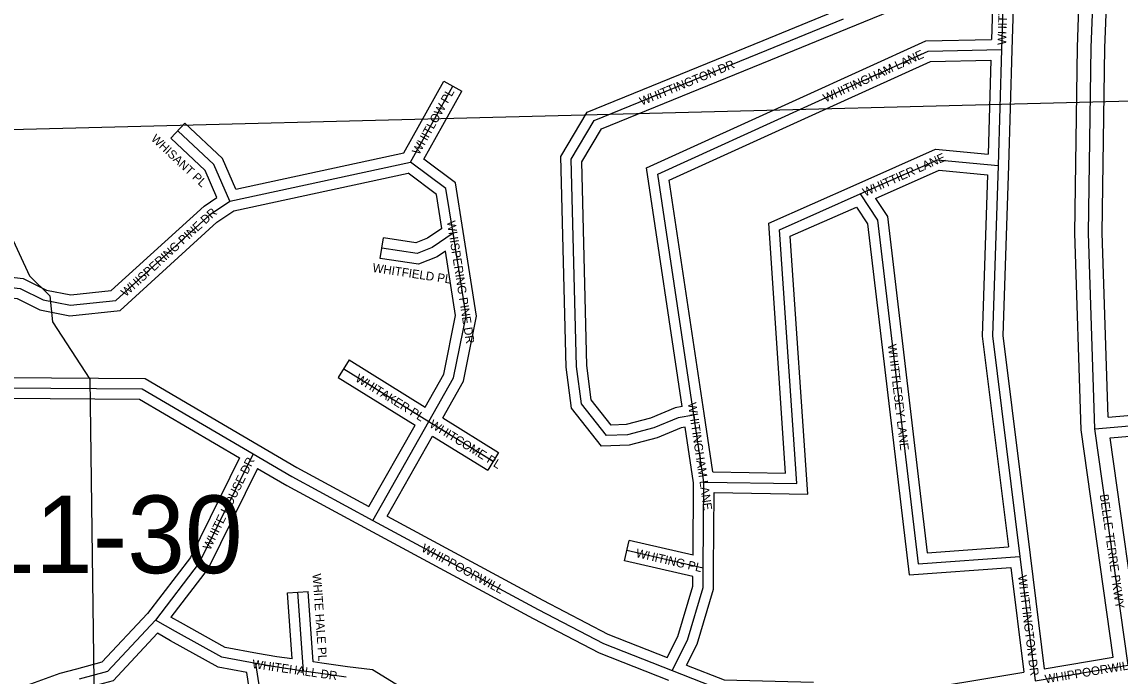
# Model space of a CAD drawing. Extents: x 457167 to 656239, y 1787309 to 1969297.
# Drawn here: x 581357 to 584541, y 1885990 to 1887885 of the extents above; entities that cross this region are included whole.
import ezdxf

# ---------------------------------------------------------------- set-up
doc = ezdxf.new("R2010")
doc.units = 0
for name, color, linetype in [('Level 1', 7, 'Continuous'), ('Level 2', 7, 'Continuous'), ('Level 22', 7, 'Continuous'), ('Level 23', 7, 'Continuous'), ('Level 31', 7, 'Continuous'), ('Level 32', 7, 'Continuous'), ('Level 34', 7, 'Continuous'), ('Level 7', 7, 'Continuous')]:
    doc.layers.add(name, color=color, linetype=linetype)

msp = doc.modelspace()

# ---------------------------------------------------------------- linework, layer by layer
at = {"layer": 'Level 1'}
msp.add_line((585126.331, 1887669.13), (579922.889, 1887536.016), dxfattribs=at)
at = {"layer": 'Level 22'}
for p, q in [((584457.098, 1887810.93), (584472.847, 1888226.538)), ((584564.332, 1886020.891), (584467.69, 1886706.173))]:
    msp.add_line(p, q, dxfattribs=at)
msp.add_lwpolyline([(584467.69, 1886706.173), (584449.383, 1887273.122), (584457.098, 1887810.93)], dxfattribs=at)
at = {"layer": 'Level 23'}
for p, q in [((584417.109, 1887811.974), (584432.875, 1888228.053)), ((584497.089, 1887809.885), (584512.819, 1888225.023)), ((584520.675, 1886044.017), (584427.782, 1886702.724)), ((584603.599, 1886028.903), (584511.802, 1886679.831))]:
    msp.add_line(p, q, dxfattribs=at)
for points in [[(584427.781, 1886702.725), (584409.373, 1887272.763), (584417.109, 1887811.974)], [(584506.633, 1886739.61), (584489.392, 1887273.481), (584497.089, 1887809.885)]]:
    msp.add_lwpolyline(points, dxfattribs=at)
at = {"layer": 'Level 31'}
for p, q in [((584206.055, 1888084.51), (584197.564, 1887804.888)), ((583516.949, 1887803.307), (583739.438, 1887894.145)), ((583016.266, 1887599.564), (583516.949, 1887803.307)), ((584197.564, 1887804.888), (584187.054, 1887469.269)), ((582483.302, 1887478.801), (582605.867, 1887698.56)), ((583200.746, 1887444.29), (583625.077, 1887636.912)), ((581959.255, 1887365.665), (582483.302, 1887478.801)), ((583305.287, 1886745.896), (583200.746, 1887444.29)), ((582289.695, 1886879.91), (582536.836, 1886727.052)), ((582374.698, 1886440.828), (582536.836, 1886727.052)), ((582536.836, 1886727.052), (582723.306, 1886612.136)), ((583334.167, 1886551.657), (583305.287, 1886745.896)), ((583332.406, 1886301.841), (583334.167, 1886551.657)), ((583332.406, 1886301.841), (583110.504, 1886353.187)), ((584250.699, 1886336.046), (584295.168, 1885975.957)), ((582172.819, 1886004.136), (582157.053, 1886232.896)), ((584295.168, 1885975.957), (584564.332, 1886020.891))]:
    msp.add_line(p, q, dxfattribs=at)
for points in [[(583625.077, 1887636.912), (583984.466, 1887800.575), (584197.564, 1887804.888)], [(583305.287, 1886745.896), (583259.471, 1886737.623), (583189.125, 1886708.671), (583113.072, 1886688.82), (583051.365, 1886686.396), (582979.029, 1886778.176), (582965.249, 1886886.931), (582949.574, 1887487.331), (583016.266, 1887599.564)], [(581959.255, 1887365.665), (581913.351, 1887471.94), (581808.909, 1887569.605)], [(583787.746, 1887386.411), (584011.207, 1887485.611), (584187.054, 1887469.269)], [(582606.933, 1887272.736), (582586.197, 1887401.869), (582483.302, 1887478.801)], [(584187.054, 1887469.269), (584171.151, 1886975.478), (584250.699, 1886336.046)], [(583334.167, 1886551.657), (583603.232, 1886547.128), (583553.461, 1887282.868), (583787.746, 1887386.411)], [(583787.746, 1887386.411), (583837.214, 1887310.313), (583955.503, 1886314.802), (584250.699, 1886336.046)], [(581243.166, 1887125.286), (581351.276, 1887112.341), (581418.319, 1887079.477), (581497.164, 1887064.046), (581628.864, 1887077.598), (581903.522, 1887327.958), (581959.255, 1887365.665)], [(582606.933, 1887272.736), (582546.739, 1887231.401), (582502.815, 1887214.033), (582400.434, 1887229.51)], [(582536.836, 1886727.052), (582608.331, 1886854.184), (582644.625, 1887033.386), (582606.933, 1887272.736)], [(581196.746, 1886817.377), (581307.761, 1886824.79), (581705.637, 1886821.441), (582026.812, 1886633.524)], [(584467.69, 1886706.173), (584713.267, 1886727.153), (585177.477, 1886817.535)], [(582026.812, 1886633.524), (581870.971, 1886317.47), (581743.734, 1886151.178)], [(582026.812, 1886633.524), (582139.59, 1886567.843), (582374.698, 1886440.828)], [(582374.698, 1886440.828), (582853.179, 1886182.785), (583042.865, 1886083.863), (583242.451, 1886005.287)], [(583242.451, 1886005.287), (583286.834, 1886093.201), (583331.66, 1886245.841), (583332.406, 1886301.841)], [(581743.734, 1886151.178), (581604.763, 1886002.73), (581522.66, 1885980.713)], [(582034.824, 1886025.866), (581935.944, 1886043.883), (581801.873, 1886118.335), (581743.734, 1886151.178)], [(581987.091, 1885535.05), (582028.991, 1885652.421), (582056.996, 1885819.64), (582046.444, 1885951.661), (582034.824, 1886025.866)], [(582172.819, 1886004.136), (582090.783, 1886015.936), (582034.824, 1886025.866)], [(582297.145, 1885986.797), (582222.422, 1885997.128), (582172.819, 1886004.136)], [(583242.451, 1886005.287), (583387.057, 1885948.64), (583651.351, 1885941.939)]]:
    msp.add_lwpolyline(points, dxfattribs=at)
at = {"layer": 'Level 32'}
for p, q in [((584235.746, 1888073.818), (584227.55, 1887803.976)), ((583750.77, 1887866.367), (584174.669, 1888039.302)), ((584174.669, 1888039.302), (584168.444, 1887834.305)), ((583505.609, 1887831.082), (583711.393, 1887915.099)), ((583528.289, 1887775.531), (583750.778, 1887866.37)), ((582995.625, 1887623.553), (583505.642, 1887831.096)), ((584227.549, 1887803.948), (584217.041, 1887468.329)), ((583036.909, 1887575.574), (583528.257, 1887775.518)), ((584166.59, 1887774.253), (584158.068, 1887502.091)), ((582463.71, 1887505.262), (582579.666, 1887713.172)), ((582579.666, 1887713.172), (582632.068, 1887683.946)), ((582522.289, 1887487.111), (582632.068, 1887683.946)), ((583167.724, 1887462.246), (583612.676, 1887664.23)), ((583233.769, 1887426.332), (583637.479, 1887609.594)), ((581788.418, 1887547.691), (581829.399, 1887591.518)), ((581977.022, 1887400.191), (582463.71, 1887505.262)), ((583271.308, 1886770.246), (583167.724, 1887462.246)), ((581971.26, 1887337.563), (582476.28, 1887446.591)), ((583334.957, 1886750.337), (583233.769, 1887426.332)), ((582395.95, 1887199.846), (582404.918, 1887259.173)), ((582305.475, 1886905.424), (582273.915, 1886854.395)), ((582305.475, 1886905.424), (582526.018, 1886769.017)), ((582273.915, 1886854.395), (582496.506, 1886716.721)), ((583360.101, 1886581.226), (583334.961, 1886750.308)), ((582363.088, 1886481.198), (582496.505, 1886716.721)), ((582577.115, 1886737.469), (582739.046, 1886637.676)), ((582415.9, 1886452.692), (582547.598, 1886685.18)), ((582547.598, 1886685.18), (582707.567, 1886586.596)), ((583304.152, 1886549.543), (583280.165, 1886710.872)), ((582739.046, 1886637.676), (582707.567, 1886586.596)), ((583302.671, 1886339.513), (583304.152, 1886549.543)), ((583362.407, 1886301.628), (583363.954, 1886521.15)), ((583103.742, 1886323.958), (583117.268, 1886382.416)), ((583302.671, 1886339.513), (583117.268, 1886382.416)), ((584280.474, 1886339.721), (584321.106, 1886010.701)), ((583302.088, 1886278.062), (583103.742, 1886323.958)), ((584224.42, 1886304.076), (584261.863, 1886000.878)), ((582127.124, 1886230.834), (582186.982, 1886234.958)), ((582140.337, 1886039.118), (582127.124, 1886230.834)), ((582201.078, 1886030.441), (582186.982, 1886234.958)), ((584321.106, 1886010.702), (584520.675, 1886044.017)), ((583895.139, 1885940.51), (584261.863, 1886000.878))]:
    msp.add_line(p, q, dxfattribs=at)
for points in [[(583612.644, 1887664.216), (583977.669, 1887830.444), (584168.444, 1887834.304)], [(583637.51, 1887609.609), (583991.264, 1887770.706), (584166.59, 1887774.253)], [(583280.165, 1886710.872), (583267.941, 1886708.666), (583198.665, 1886680.156), (583117.5, 1886658.971), (583037.266, 1886655.819), (582950.314, 1886766.146), (582935.298, 1886884.649), (582919.358, 1887495.21), (582995.625, 1887623.553)], [(581977.022, 1887400.191), (581938.411, 1887489.579), (581829.399, 1887591.518)], [(581921.859, 1887376.586), (581888.291, 1887454.3), (581788.418, 1887547.691)], [(583271.309, 1886770.246), (583251.002, 1886766.579), (583179.584, 1886737.186), (583108.643, 1886718.67), (583065.464, 1886716.974), (583007.745, 1886790.208), (582995.2, 1886889.214), (582979.791, 1887479.453), (583036.909, 1887575.574)], [(583775.573, 1887413.831), (584006.189, 1887516.208), (584158.068, 1887502.091)], [(582636.554, 1887277.492), (582613.891, 1887418.621), (582522.289, 1887487.111)], [(583832.074, 1887373.264), (584016.224, 1887455.015), (584156.161, 1887442.009)], [(584217.039, 1887468.303), (584201.211, 1886976.856), (584280.47, 1886339.749)], [(582574.304, 1887286.72), (582558.503, 1887385.116), (582476.28, 1887446.591)], [(584156.161, 1887442.01), (584141.09, 1886974.101), (584217.028, 1886363.701)], [(583360.102, 1886581.225), (583571.097, 1886577.674), (583522.111, 1887301.813), (583775.619, 1887413.851)], [(581259.908, 1887153.496), (581359.904, 1887141.522), (581427.966, 1887108.159), (581498.539, 1887094.346), (581615.959, 1887106.43), (581884.914, 1887351.591), (581921.859, 1887376.585)], [(583832.074, 1887373.264), (583866.179, 1887320.799), (583981.914, 1886346.781), (584217.028, 1886363.701)], [(581259.723, 1887093.089), (581342.649, 1887083.159), (581408.67, 1887050.796), (581495.789, 1887033.745), (581641.769, 1887048.767), (581922.129, 1887304.326), (581971.26, 1887337.563)], [(583363.954, 1886521.151), (583635.367, 1886516.583), (583584.812, 1887263.924), (583776.514, 1887348.646)], [(583776.514, 1887348.646), (583808.248, 1887299.826), (583929.091, 1886282.823), (584224.419, 1886304.075)], [(582574.304, 1887286.72), (582532.554, 1887258.051), (582499.304, 1887244.906), (582404.918, 1887259.173)], [(582577.115, 1886737.469), (582636.797, 1886843.597), (582675.1, 1887032.721), (582636.568, 1887277.403)], [(582584.699, 1887221.073), (582560.926, 1887204.749), (582506.326, 1887183.161), (582395.95, 1887199.846)], [(582526.018, 1886769.017), (582579.866, 1886864.771), (582614.151, 1887034.051), (582584.699, 1887221.073)], [(581224.194, 1886849.277), (581306.886, 1886854.799), (581713.884, 1886851.374), (582041.962, 1886659.418)], [(584506.633, 1886739.61), (584709.111, 1886756.908), (585134.412, 1886839.713)], [(581198.745, 1886787.443), (581308.635, 1886794.781), (581697.389, 1886791.51), (581987.552, 1886621.736)], [(584511.802, 1886679.831), (584717.422, 1886697.399), (585183.211, 1886788.086)], [(582041.91, 1886659.449), (582154.273, 1886594.01), (582363.088, 1886481.198)], [(581987.552, 1886621.736), (581845.362, 1886333.37), (581720.814, 1886170.592)], [(582039.499, 1886591.416), (581896.579, 1886301.57), (581788.517, 1886160.336)], [(582039.5, 1886591.417), (582124.908, 1886541.676), (582360.439, 1886414.433)], [(582415.9, 1886452.692), (582867.236, 1886209.29), (583055.331, 1886111.197), (583227.995, 1886043.22)], [(582360.458, 1886414.422), (582839.123, 1886156.28), (583030.399, 1886056.53), (583231.461, 1885977.372)], [(583227.995, 1886043.22), (583258.819, 1886104.279), (583301.718, 1886250.351), (583302.088, 1886278.061)], [(583284.09, 1886021.196), (583314.848, 1886082.122), (583361.604, 1886241.331), (583362.404, 1886301.441)], [(581720.814, 1886170.592), (581588.717, 1886029.488), (581514.889, 1886009.691)], [(582040.202, 1886055.381), (581946.186, 1886072.511), (581816.532, 1886144.51), (581788.518, 1886160.336)], [(581749.516, 1886113.455), (581620.809, 1885975.971), (581563.052, 1885960.483)], [(582008.483, 1886000.171), (581925.703, 1886015.255), (581787.213, 1886092.16), (581749.515, 1886113.455)], [(582140.337, 1886039.118), (582095.541, 1886045.561), (582040.202, 1886055.381)], [(582301.004, 1886016.549), (582226.574, 1886026.84), (582201.078, 1886030.441)], [(582715.22, 1884754.296), (582751.389, 1884803.925), (582842.564, 1885097.396), (582778.781, 1885401.342), (582679.743, 1885677.827), (582520.871, 1885916.901), (582372.83, 1886007.234), (582301.004, 1886016.549)], [(583284.09, 1886021.196), (583393.089, 1885978.496), (583652.111, 1885971.93)], [(581515.049, 1886009.732), (581466.947, 1885997.116), (581263.648, 1885923.461), (581010.399, 1885899.701), (580879.968, 1885895.633)], [(581963.511, 1885558.226), (581999.842, 1885660.001), (582026.795, 1885820.941), (582016.63, 1885948.141), (582008.483, 1886000.171)]]:
    msp.add_lwpolyline(points, dxfattribs=at)
at = {"layer": 'Level 7'}
msp.add_lwpolyline([(581312.606, 1887291.545), (581379.139, 1887149.761), (581437.431, 1887091.341), (581445.702, 1887016.278), (581553.876, 1886849.455), (581569.312, 1885682.327), (581610.706, 1885398.861), (581635.687, 1885373.82), (581627.02, 1885073.712), (581776.49, 1884531.68)], dxfattribs=at)

# ---------------------------------------------------------------- texts
at = {"layer": 'Level 2'}
msp.add_text('25-11-30', height=225, dxfattribs=at).set_placement((580792.309, 1886287.787))
at = {"layer": 'Level 34'}
for s, height, rotation, p in [('WHITTINGTON DR', 25, 88.259689, (584210.459, 1887817.764)), ('WHITINGHAM LANE', 25, 24.483492, (583686.984, 1887651.371)), ('WHITTINGTON DR', 25, 22.142392, (583154.043, 1887642.136)), ('WHITLOW PL', 25, 60.849672, (582508.325, 1887498.008)), ('WHISANT PL', 25, 316.920261, (581729.199, 1887543.87)), ('WHITTIER LANE', 25, 23.937297, (583801.347, 1887378.772)), ('WHISPERING PINE DR', 25, 42.349314, (581657.994, 1887087.241)), ('WHISPERING PINE DR', 25, 278.948728, (582588.886, 1887306.991)), ('WHITFIELD PL', 25, 351.403619, (582372.069, 1887160.948)), ('WHITTLESEY LANE', 25, 276.775572, (583867.446, 1886949.949)), ('WHITAKER PL', 25, 328.263003, (582321.509, 1886845.535)), ('WHITINGHAM LANE', 25, 278.456353, (583287.494, 1886780.588)), ('WHITCOME PL', 25, 328.355364, (582536.236, 1886712.74)), ('WHITE HOUSE DR', 25, 63.751906, (581902.225, 1886352.596)), ('BELLE TERRE PKWY', 24.99916, 278.026453, (584482.063, 1886514.755)), ('WHIPPOORWILL', 25, 331.662061, (582512.781, 1886352.158)), ('WHITING PL', 25, 346.971297, (583135.327, 1886334.613)), ('WHITE HALE PL', 25, 273.941772, (582199.229, 1886285.831)), ('WHITTINGTON DR', 25, 277.039256, (584245.011, 1886280.13)), ('WHITEHALL DR', 25, 351.814211, (582022.934, 1886013.068)), ('WHIPPOORWILL', 25, 9.477028, (584325.095, 1885968.281))]:
    msp.add_text(s, height=height, rotation=rotation, dxfattribs=at).set_placement(p)

doc.saveas('drawing.dxf')
